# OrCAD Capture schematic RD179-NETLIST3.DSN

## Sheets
1 3: size A3
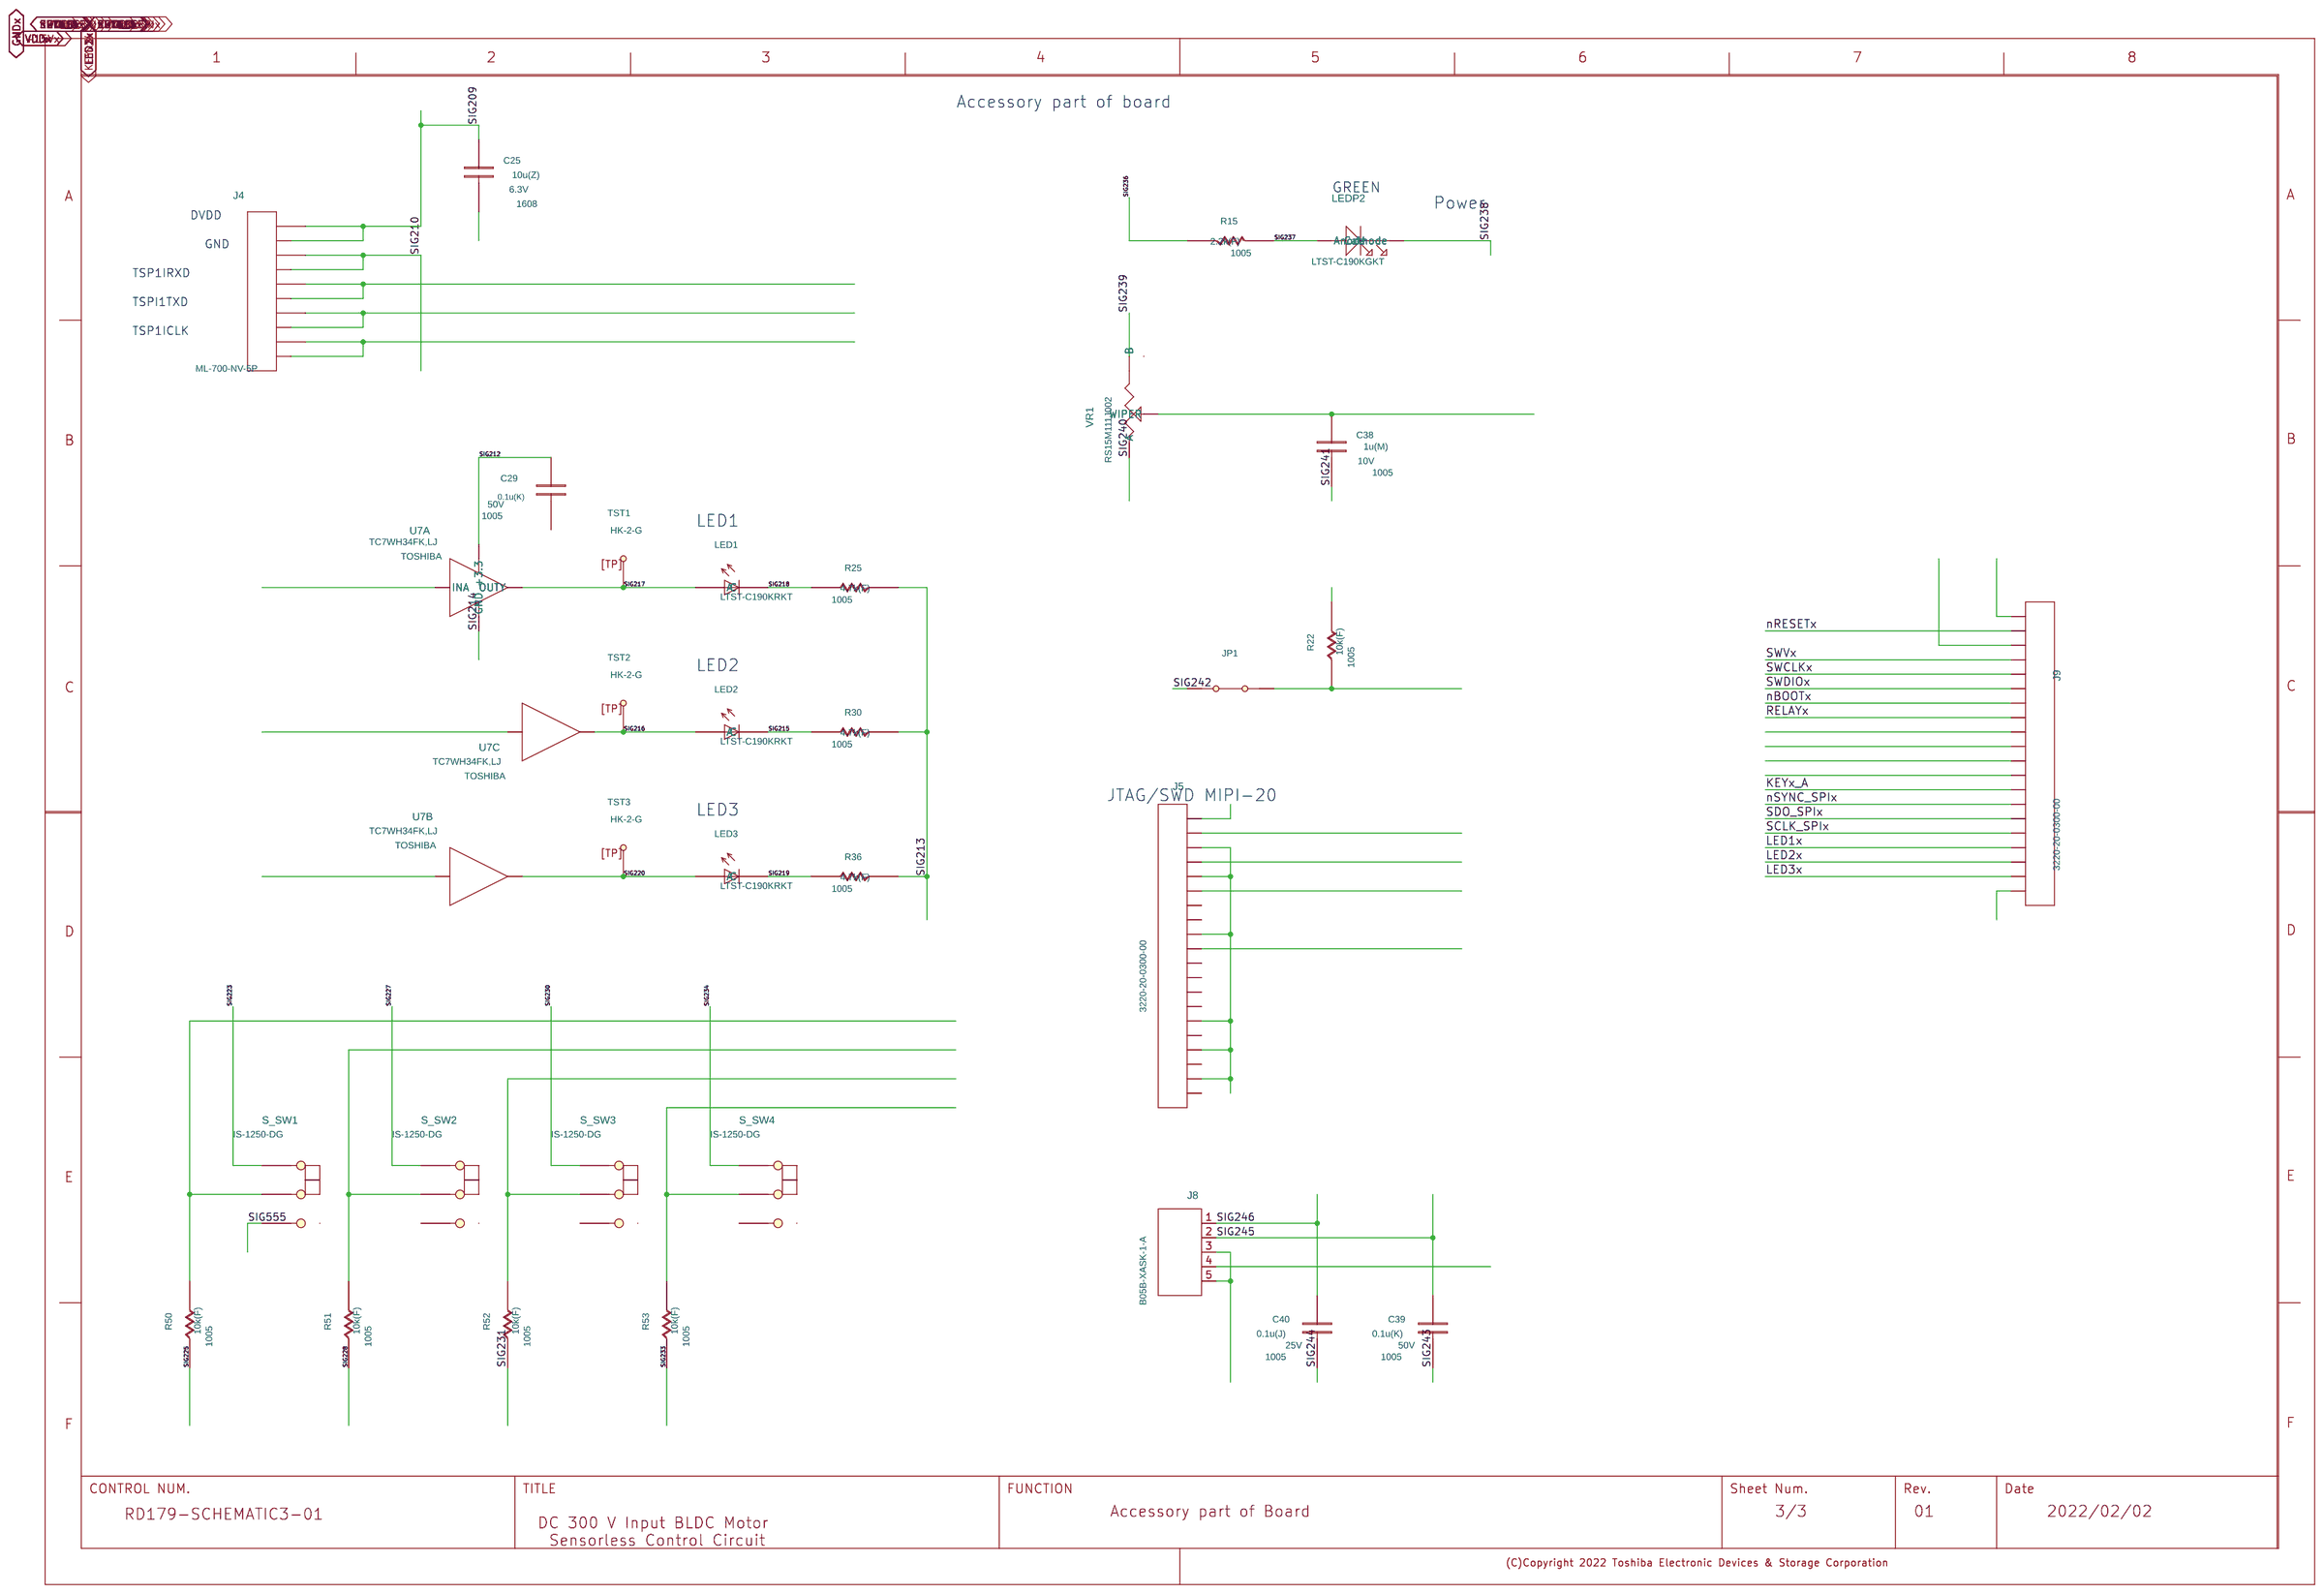
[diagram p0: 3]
2 2: size A3
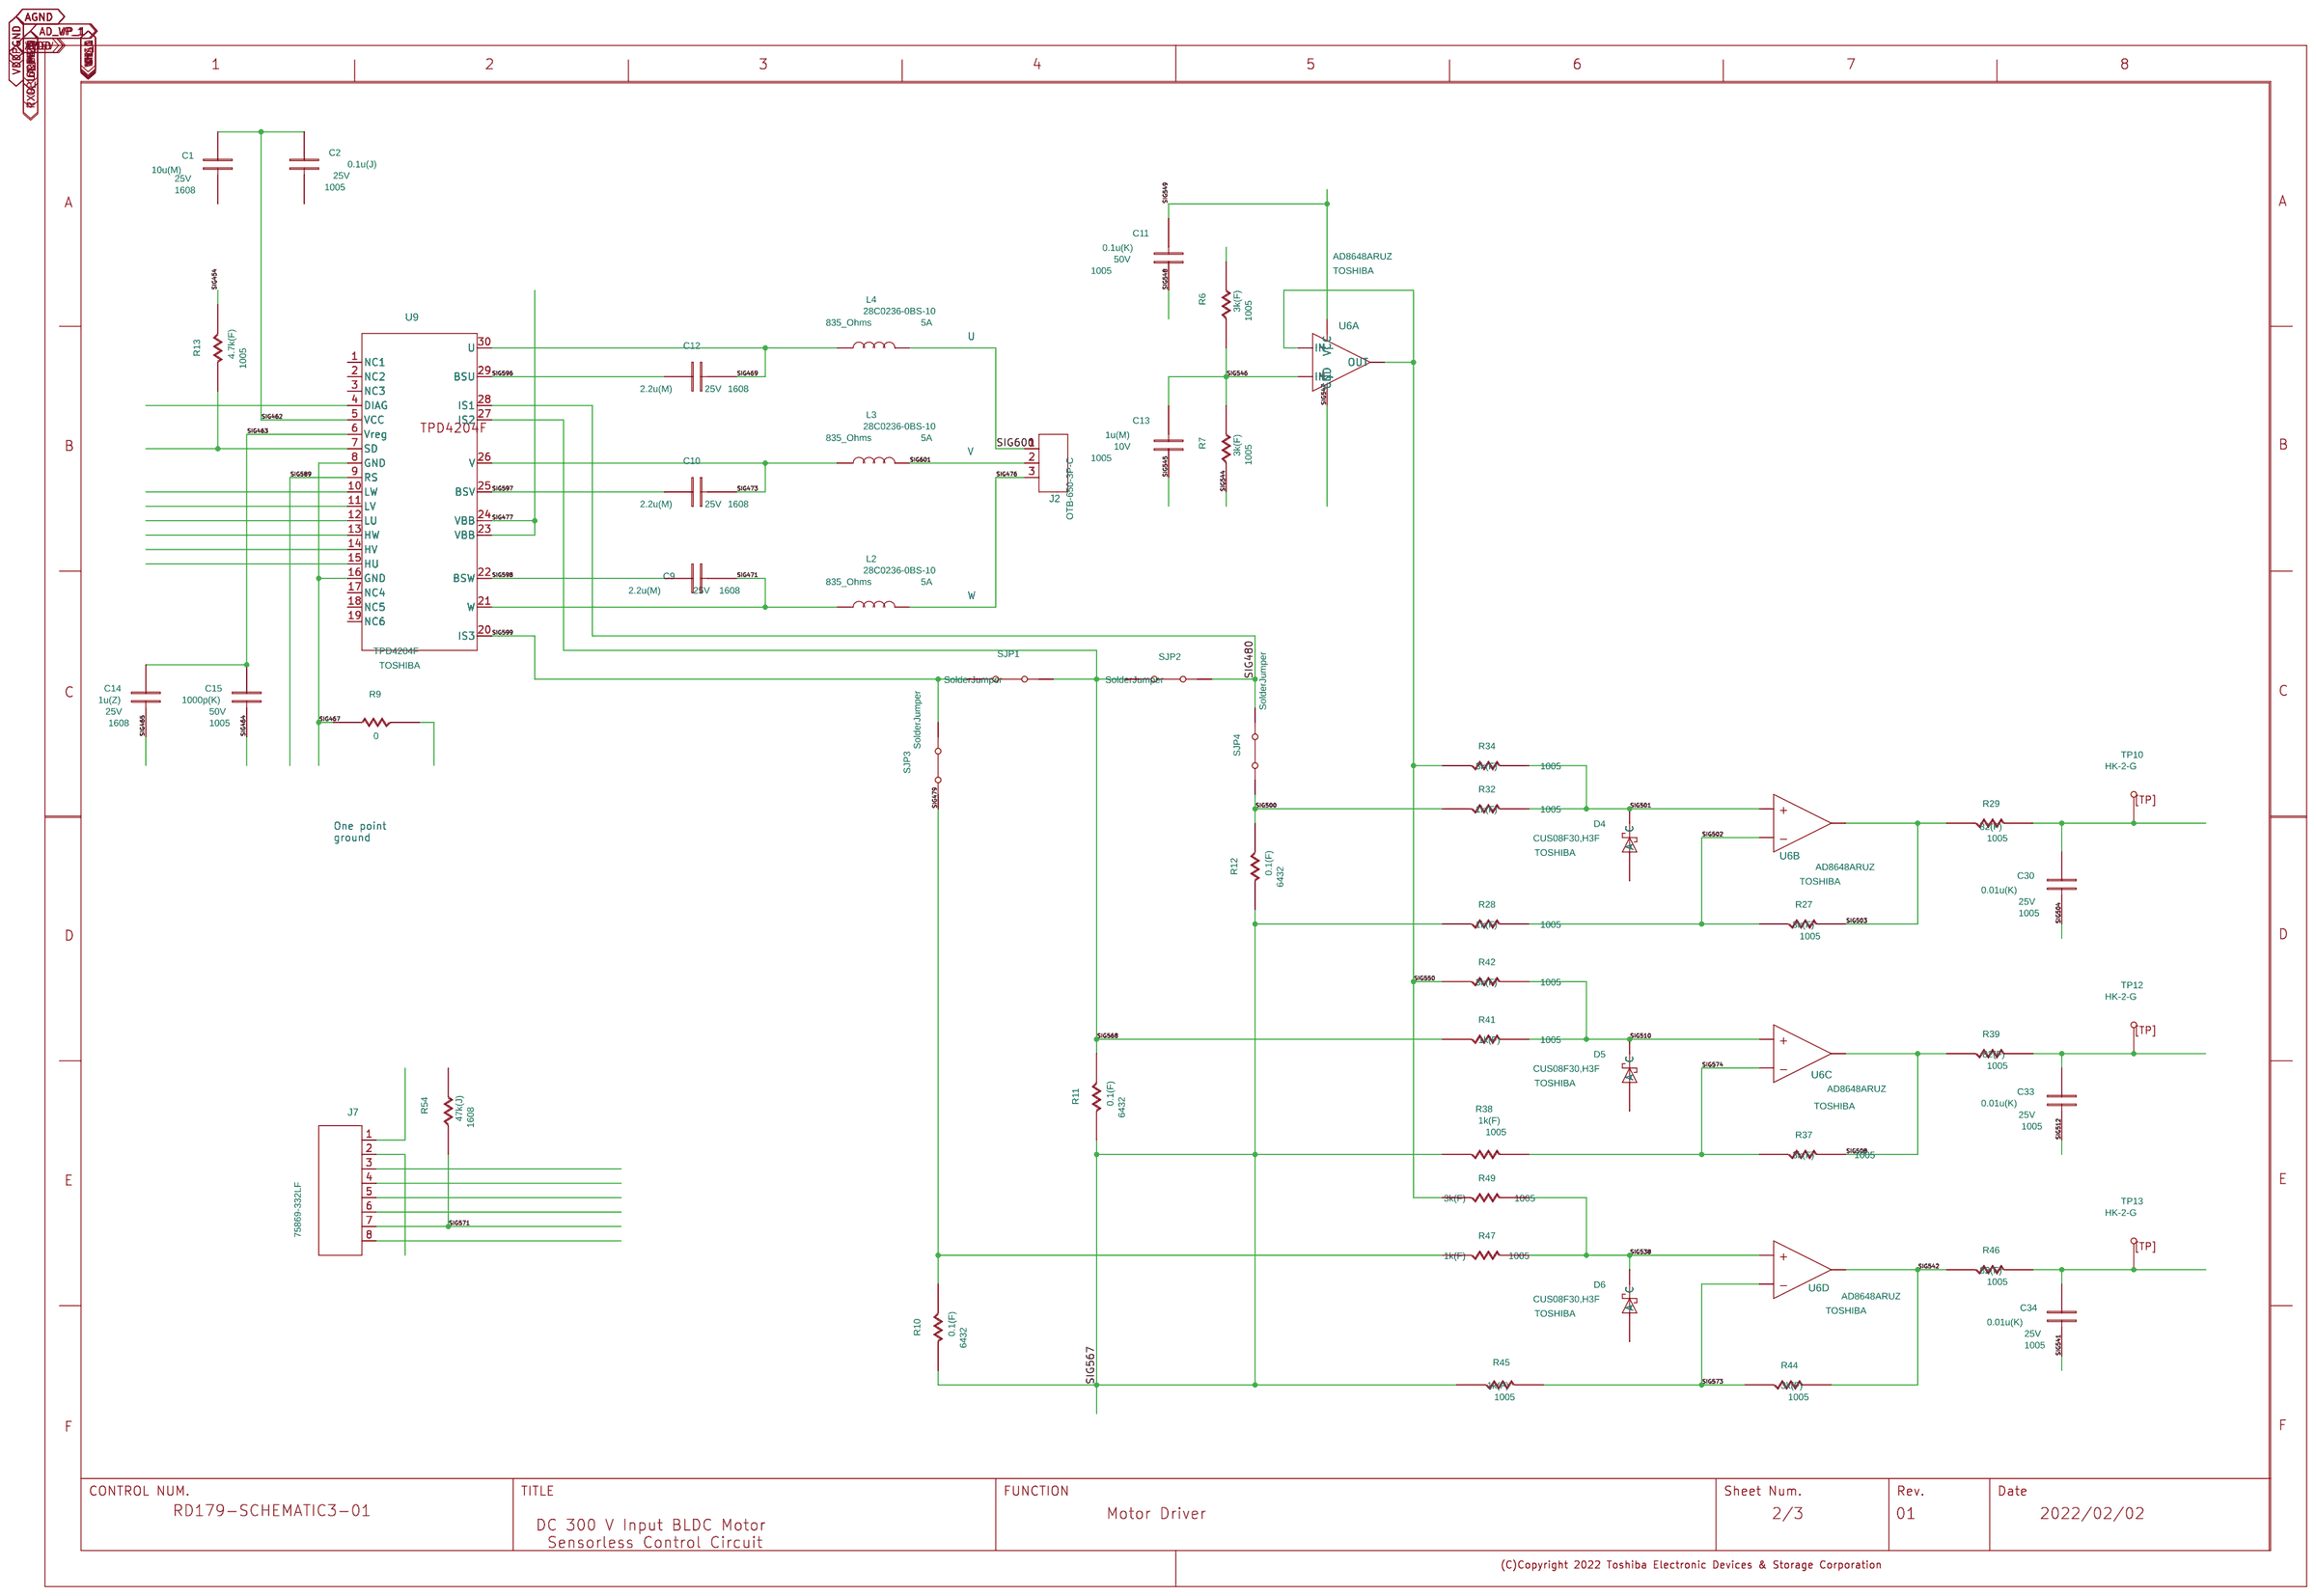
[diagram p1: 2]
3 1: size A3
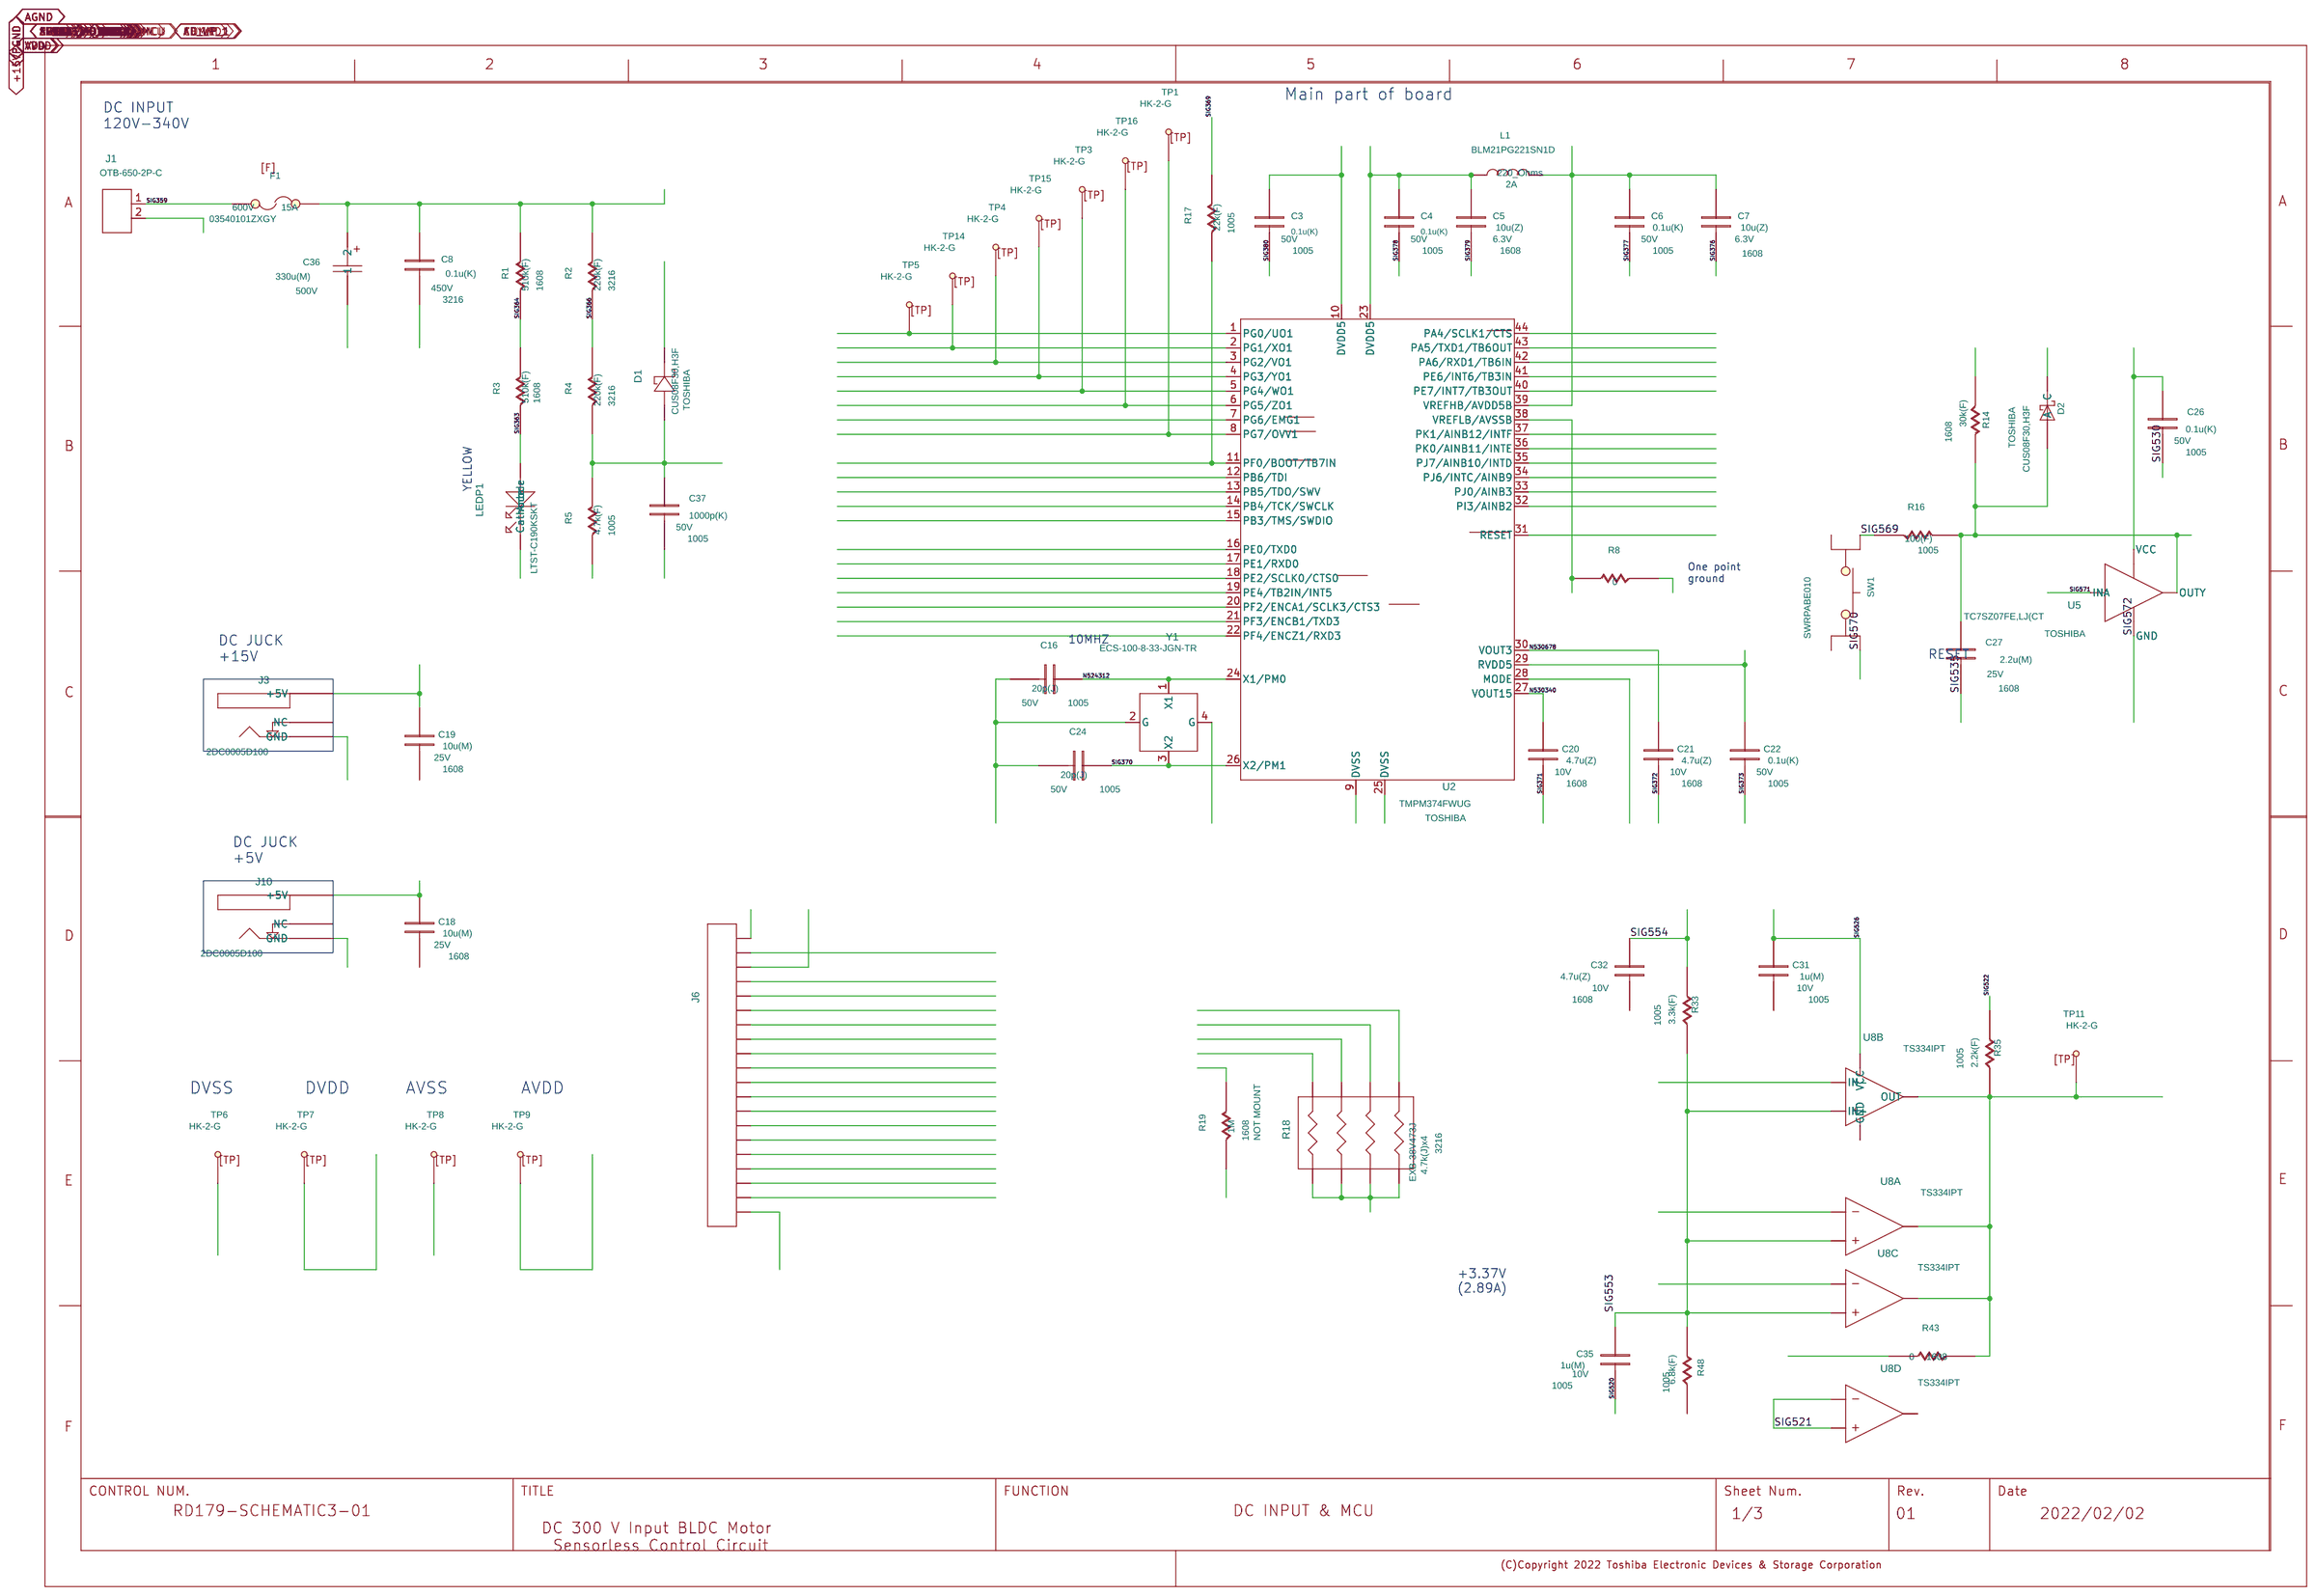
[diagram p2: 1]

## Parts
sheet 1
C3  C
C4  C
C5  C
C6  C
C7  C
C8  C
C16  C
C18  C
C19  C
C20  C
C21  C
C22  C
C24  C
C26  C
C27  C
C31  C
C32  C
C35  C
C36  CP
C37  C
D1  CUS08F30
D2  SBD
F1  F
J1  OTB-650-2P-C
J3  DCJACK
J6  3220-20-0300-00
J10  DCJACK
L1  L
LEDP1  LTST-C190KSKT  [LED]
R1  R
R2  R
R3  R
R4  R
R5  R
R8  R
R14  R
R16  R
R17  R
R18  EXB-38V473J
R19  R
R33  R
R35  R
R43  R
R48  R
SW1  SWRPABE010
TP1  TP
TP3  TP
TP4  TP
TP5  TP
TP6  TP
TP7  TP
TP8  TP
TP9  TP
TP11  TP
TP14  TP
TP15  TP
TP16  TP
U2  TMPM374FWUG
U5  SN74LVC1G07DRLR_1
U8  LMV339IPT_2  (sections A,B,C,D)
U?#2  WAKU_DEF100
Y1  XTAL_ECS_100_8_33_10_000MHZ
sheet 2
C1  C
C2  C
C9  C
C10  C
C11  C
C12  C
C13  C
C14  C
C15  C
C30  C
C33  C
C34  C
D4  SBD
D5  SBD
D6  SBD
J2  OTB-650-3P-C
J7  75869-332LF
L2  L
L3  L
L4  L
R6  R
R7  R
R9  R
R10  R
R11  R
R12  R
R13  R
R27  R
R28  R
R29  R
R32  R
R34  R
R37  R
R38  R
R39  R
R41  R
R42  R
R44  R
R45  R
R46  R
R47  R
R49  R
R54  R
SJP1  JP
SJP2  JP
SJP3  JP
SJP4  JP
TP10  TP
TP12  TP
TP13  TP
U6  AD8648ARUZ_1  (sections A,B,C,D)
U9  TPD4204F
U?#1  WAKU_DEF100
sheet 3
C25  C
C29  C
C38  C
C39  C
C40  C
J4  ML_700_NH_5P
J5  3220-20-0300-00
J8  B05B-XASK-1-A
J9  3220-20-0300-00
JP1  JP
LED1  LED
LED2  LED
LED3  LED
LEDP2  LTST-C190KGKT  [LED]
R15  R
R22  R
R25  R
R30  R
R36  R
R50  R
R51  R
R52  R
R53  R
S_SW1  SW_IS_1250
S_SW2  SW_IS_1250
S_SW3  SW_IS_1250
S_SW4  SW_IS_1250
TST1  TP
TST2  TP
TST3  TP
U7  SN74LVC3G17DCUR_1  (sections A,B,C)
U?#3  WAKU_DEF100
VR1  VR

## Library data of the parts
C3 C4 C6 C11 C22 C26 C29 C39 = C: COMP: CRC-1005-DEF; COMPONENTTYPE: 4; SIZECODESMD: 1005; VAL1: 0.1u(K); VAL2: 50V
C5 C7 C25 = C: COMP: CRC-1608-DEF; COMPONENTTYPE: 4; SIZECODESMD: 1608; VAL1: 10u(Z); VAL2: 6.3V
C8 = C: COMP: CC-3216-DEF; COMPONENTTYPE: 4; SIZECODESMD: 3216; VAL1: 0.1u(K); VAL2: 450V
C16 C24 = C: COMP: CRC-1005-DEF; COMPONENTTYPE: 4; SIZECODESMD: 1005; VAL1: 20p(J); VAL2: 50V
C1 C18 C19 = C: COMP: CRC-1608-DEF; COMPONENTTYPE: 4; SIZECODESMD: 1608; VAL1: 10u(M); VAL2: 25V
C20 C21 C32 = C: COMP: CRC-1608-DEF; COMPONENTTYPE: 4; SIZECODESMD: 1608; VAL1: 4.7u(Z); VAL2: 10V
C9 C10 C12 C27 = C: COMP: CRC-1608-DEF; COMPONENTTYPE: 4; SIZECODESMD: 1608; VAL1: 2.2u(M); VAL2: 25V
C13 C31 C35 C38 = C: COMP: CRC-1005-DEF; COMPONENTTYPE: 4; SIZECODESMD: 1005; VAL1: 1u(M); VAL2: 10V
C36 = CP: COMP: DDC-3000-00; COMPONENTTYPE: 4; VAL1: 330u(M); VAL2: 500V
C15 C37 = C: COMP: CRC-1005-DEF; COMPONENTTYPE: 4; SIZECODESMD: 1005; VAL1: 1000p(K); VAL2: 50V
D1 = DIODE_SB1003M3: COMP: CD-USC-05; COMPONENTTYPE: 4; INSTANCENAME: I16849034; TIME: 16:32:01; UPDATETIME: 16:32:01; USERCOMPTEXT3: TOSHIBA; VAL1: CUS08F30,H3F; VAL3: CUS08F30,H3F
D2 D4-D6 = SBD: COMP: CD-USC-05; COMPONENTTYPE: 4; USERCOMPTEXT3: TOSHIBA; VAL1: CUS08F30,H3F; VAL3: CUS08F30,H3F
F1 = F: COMP: DFU-3512-00; COMPONENTTYPE: 4; VAL1: 600V; VAL2: 15A; VAL3: 03540101ZXGY
J1 = OTB_650_2P_C: COMP: OTB-650-2P_R00; COMPONENTTYPE: 4; INSTANCENAME: I00689; SAVECOUNT: 1; UPDATETIME: 16:32:00
J3 = DCJACK: COMP: 2DC-0005D100_R00; COMPONENTTYPE: 4; INSTANCENAME: I16855658; SAVECOUNT: 1; UPDATETIME: 16:32:01; VAL1: 2DC0005D100; VAL3: 2DC0005D100
J6 = CON20: COMP: 3220-20-0300-00_R00; COMPONENTKIND: 135; COMPONENTTYPE: 4; INSTANCENAME: I17020784; SAVECOUNT: 1; UPDATETIME: 16:32:01
J10 = DCJACK: COMP: 2DC-0005D100_R00; COMPONENTTYPE: 4; INSTANCENAME: I17047111; SAVECOUNT: 1; UPDATETIME: 16:32:01; VAL1: 2DC0005D100; VAL3: 2DC0005D100
L1 = L: COMP: CL-2125-DEF; COMPONENTTYPE: 4; VAL1: 220_Ohms; VAL2: 2A; VAL3: BLM21PG221SN1D
LEDP1 = LED_3RED: COMP: LTST-C190_R00; COMPONENTKIND: 104; COMPONENTTYPE: 4; INSTANCENAME: I16843725
R1 R3 = R: COMP: CRC-1608-DEF; COMPONENTTYPE: 4; SIZECODESMD: 1608; VAL1: 510k(F); VAL2: 250mW
R2 R4 = R: COMP: CR-3216-DEF; COMPONENTTYPE: 4; SIZECODESMD: 3216; VAL1: 220k(F); VAL2: 250mW
R5 R13 R25 R30 R36 = R: COMP: CRC-1005-DEF; COMPONENTTYPE: 4; SIZECODESMD: 1005; VAL1: 4.7k(F); VAL2: 63mW
R8 R9 = R: COMP: CX-0002-75; COMPONENTTYPE: 4; VAL1: 0
R14 = R: COMP: CRC-1608-58; COMPONENTTYPE: 4; SIZECODESMD: 1608; VAL1: 30k(F); VAL2: 100mW
R16 = R: COMP: CRC-1005-DEF; COMPONENTTYPE: 4; SIZECODESMD: 1005; VAL1: 100(F); VAL2: 100mW
R17 = R: COMP: CRC-1005-DEF; COMPONENTTYPE: 4; SIZECODESMD: 1005; VAL1: 22k(F); VAL2: 100mW
R18 = EXB_38V: COMP: CRA-3216-33; COMPONENTTYPE: 4; INSTANCENAME: I17038151; SAVECOUNT: 1; SIZECODESMD: 3216; UPDATETIME: 16:32:00; VAL1: 4.7k(J)x4; VAL2: 63w
R19 = R: COMP: CRC-1608-DEF; COMPONENTTYPE: 4; NOTMOUNT: NOT MOUNT; SIZECODESMD: 1608; VAL1: 1M; VAL2: 100mW
R33 = R: COMP: CRC-1005-DEF; COMPONENTTYPE: 4; SIZECODESMD: 1005; VAL1: 3.3k(F); VAL2: 100mW
R15 R35 = R: COMP: CRC-1005-DEF; COMPONENTTYPE: 4; SIZECODESMD: 1005; VAL1: 2.2k(F); VAL2: 100mW
R43 = R: COMP: CRC-1608-DEF; COMPONENTTYPE: 4; SIZECODESMD: 1608; VAL1: 0; VAL2: 100mW
R48 = R: COMP: CRC-1005-12; COMPONENTTYPE: 4; SIZECODESMD: 1005; VAL1: 6.8k(F); VAL2: 63mW
SW1 = SWRPABE010: COMP: SKRPABE010_R01; COMPONENTTYPE: 4
TP1 TP3-TP16 TST1-TST3 = TP: COMP: HK-2-G; COMPONENTTYPE: 4; VAL1: HK-2-G; VAL3: HK-2-G
U2 = TMPM374FWUG: COMPONENTTYPE: 4; USERCOMPTEXT3: TOSHIBA
U5 = SN74LVC1G07DRLR_1: COMP: TC7SZ07FE; COMPONENTKIND: 101; COMPONENTTYPE: 4; USERCOMPTEXT3: TOSHIBA; VAL1: TC7SZ07FE,LJ(CT; VAL3: TC7SZ07FE,LJ(CT
U8 = LMV339IPT_2: COMP: TS334IPT; COMPONENTTYPE: 8; CaptureCellPackProp: LMV339IPT_2A; FUNCN: TS334IPT_2; VAL1: TS334IPT; VAL3: TS334IPT
U?#2 = WAKU_DEF100: COMPONENTTYPE: 2; DATE: 2022/02/02; DRAWINGNUMBER: RD179-SCHEMATIC3-01; FUNCTION: DC INPUT & MCU; REVISION: 01; SAVEAREA0: 147884,-66467,487065,89883; SAVECOUNT: 7; SHEETNUMBER: 1/3; TITLE: DC 300 V Input BLDC Motor / Sensorless Control Circuit; UPDATEDATE: 2022/02/03; UPDATETIME: 12:53:04
Y1 = XTAL_ECS_100_8_33_10_000MHZ: COMP: CXL-3225-68; COMPONENTKIND: 101; COMPONENTTYPE: 4; VAL1: ECS-100-8-33-JGN-TR; VAL3: ECS-100-8-33-JGN-TR
C2 C40 = C: COMP: CRC-1005-DEF; COMPONENTTYPE: 4; SIZECODESMD: 1005; VAL1: 0.1u(J); VAL2: 25V
C14 = C: COMP: CRC-1608-DEF; COMPONENTTYPE: 4; SIZECODESMD: 1608; VAL1: 1u(Z); VAL2: 25V
C30 C33 C34 = C: COMP: CRC-1005-DEF; COMPONENTTYPE: 4; SIZECODESMD: 1005; VAL1: 0.01u(K); VAL2: 25V
J2 = OTB_650_3P_C: COMP: OTB-650-3P_R00; COMPONENTTYPE: 4; INSTANCENAME: I541179; SAVECOUNT: 1; UPDATETIME: 16:31:59
J7 = CON8: COMP: 75869-332LF_R00; COMPONENTKIND: 135; COMPONENTTYPE: 4; INSTANCENAME: I16797633; SAVECOUNT: 1; UPDATETIME: 16:31:59
L2-L4 = L: COMP: DL-1460-01; COMPONENTTYPE: 4; VAL1: 835_Ohms; VAL2: 5A; VAL3: 28C0236-0BS-10
R6 R7 R27 R34 R37 R42 R44 R49 = R: COMP: CRC-1005-DEF; COMPONENTTYPE: 4; SIZECODESMD: 1005; VAL1: 3k(F); VAL2: 100mW
R10-R12 = R: COMP: CR-6432-18; COMPONENTTYPE: 4; SIZECODESMD: 6432; VAL1: 0.1(F); VAL2: 3W
R28 R32 R38 R41 R45 R47 = R: COMP: CRC-1005-DEF; COMPONENTTYPE: 4; SIZECODESMD: 1005; VAL1: 1k(F); VAL2: 100mW
R29 R39 R46 = R: COMP: CRC-1005-DEF; COMPONENTTYPE: 4; SIZECODESMD: 1005; VAL1: 82(F); VAL2: 63mW
R54 = R: COMP: CRC-1608-DEF; COMPONENTTYPE: 4; SIZECODESMD: 1608; VAL1: 47k(J); VAL2: 100mW
SJP1-SJP4 = JP: COMP: CJP-0002-116; COMPONENTTYPE: 4; VAL1: SolderJumper; VAL3: SolderJumper
U6 = AD8648ARUZ_1: COMPONENTTYPE: 4; CaptureCellPackProp: AD8648ARUZ_1A; USERCOMPTEXT3: TOSHIBA; VAL1: AD8648ARUZ; VAL3: AD8648ARUZ
U9 = TPD4204F: COMPONENTTYPE: 4; USERCOMPTEXT3: TOSHIBA
U?#1 = WAKU_DEF100: COMPONENTTYPE: 2; DATE: 2022/02/02; DRAWINGNUMBER: RD179-SCHEMATIC3-01; FUNCTION: Motor Driver; REVISION: 01; SAVEAREA0: 147884,-66467,487065,89883; SAVECOUNT: 7; SHEETNUMBER: 2/3; TITLE: DC 300 V Input BLDC Motor / Sensorless Control Circuit; UPDATEDATE: 2022/02/03; UPDATETIME: 11:31:06
J4 = ML_700_NH_5P: COMP: ML-700-NV-5P_R00; COMPONENTTYPE: 4; VAL1: ML-700-NV-5P; VAL3: ML-700-NV-5P
J5 = CON20: COMP: 3220-20-0300-00_R00; COMPONENTKIND: 135; COMPONENTTYPE: 4; INSTANCENAME: I16846450; SAVECOUNT: 1; UPDATETIME: 16:32:01
J8 = B05B_XASK_1_A: COMP: B05B-XASK-1-A_R00; COMPONENTKIND: 135; COMPONENTTYPE: 4; INSTANCENAME: I16947079; SAVECOUNT: 1; UPDATETIME: 16:31:59
J9 = CON20: COMP: 3220-20-0300-00_R00; COMPONENTKIND: 135; COMPONENTTYPE: 4; INSTANCENAME: I17018983; SAVECOUNT: 1; UPDATETIME: 16:32:01
JP1 = JP: COMP: PH-1X02SG_R00; COMPONENTTYPE: 4; VAL1: PH-1x40SG; VAL3: PH-1x40SG
LED1-LED3 = LED: COMP: LTST-C190_R00; COMPONENTTYPE: 4; VAL1: LTST-C190KRKT; VAL3: LTST-C190KRKT
LEDP2 = LED_3RED: COMP: LTST-C190_R00; COMPONENTKIND: 104; COMPONENTTYPE: 4; INSTANCENAME: I16847094
R22 R50-R53 = R: COMP: CRC-1005-DEF; COMPONENTTYPE: 4; SIZECODESMD: 1005; VAL1: 10k(F); VAL2: 100mW
S_SW1-S_SW4 = SW_IS_1250: COMP: IS-1250_R00; COMPONENTTYPE: 4; VAL1: IS-1250-DG; VAL3: IS-1250-DG
U7 = SN74LVC3G17DCUR_1: COMP: TC7WH34FK; COMPONENTTYPE: 8; CaptureCellPackProp: SN74LVC3G17DCUR_1B; FUNCN: TC7WH34FK_LJ_3; USERCOMPTEXT3: TOSHIBA; VAL1: TC7WH34FK,LJ; VAL3: TC7WH34FK,LJ
U?#3 = WAKU_DEF100: COMPONENTTYPE: 2; DATE: 2022/02/02; DRAWINGNUMBER: RD179-SCHEMATIC3-01; FUNCTION: Accessory part of Board; REVISION: 01; SAVEAREA0: 147884,-66467,487065,89883; SAVECOUNT: 7; SHEETNUMBER: 3/3; TITLE: DC 300 V Input BLDC Motor / Sensorless Control Circuit; UPDATEDATE: 2022/02/03; UPDATETIME: 12:53:05
VR1 = VR: COMP: RS15M111J002_R00; COMPONENTTYPE: 4; VAL1: RS15M111J002; VAL3: RS15M111J002

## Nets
+15V: C1.1 C2.1 C19.1 J3.1(+5V) J6.3 U9.5(VCC)
+15Vx: C40.1 J8.1 J9.3
AGND: C1.2 C2.2 C3.1 C3.2 C4.1 C4.2 C5.1 C5.2 C6.2 C7.2 C11.1 C13.1 C14.2 C15.2 C16.2 C18.1 C18.2 C19.2 C20.2 C21.2 C22.1 C22.2 C24.2 C26.1 C26.2 C27.2 C30.2 C31.2 C32.2 C33.2 C34.2 C35.2 D1.3(CATHODE) D2.3(C) D4.1(A) D5.1(A) D6.1(A) J3.2(GND) J6.1 J6.20 J7.1 J7.2 J10.1(+5V) J10.2(GND) L1.2 R7.2 R8.1 R8.2 R9.1 R13.2 R14.2 R17.1 R18.1 R18.2 R18.3 R18.4 R19.2 R35.1 R48.2 R54.1 SW1.4 TP6.1 TP7.1 TP8.1 U2.9(DVSS) U2.10(DVDD5) U2.23(DVDD5) U2.25(DVSS) U2.28(MODE) U2.29(RVDD5) U2.38(VREFLB/AVSSB) U5.3(GND) U5.5(VCC) U6.11(GND) U8.10 U8.11 U8.12(GND) U9.8(GND) U9.9(RS) U9.16(GND) Y1.2(G) Y1.4(G)
AVDD: C6.1 C7.1 C11.2 C31.1 C32.1 L1.1 R6.1 R33.1 TP9.1 U2.39(VREFHB/AVDD5B) U6.4(VCC) U8.3(VCC)
GNDx: C25.2 C29.2 C38.2 C39.2 C40.2 J4.2 J4.2-2 J5.3 J5.5 J5.9 J5.15 J5.17 J5.19 J8.3 J8.5 J9.20 JP1.2 LEDP2.2(Cathode) R25.2 R30.2 R36.2 R50.2 R51.2 R52.2 R53.2 S_SW1.3 S_SW2.3 S_SW3.3 S_SW4.3 U7.4(GND) VR1.1(A)
PGND: C8.2 C36.2(1) C37.2 J1.2 LEDP1.2(Cathode) R5.2 R9.2 R10.1 R11.1 R12.1 R28.2 R38.2 R45.2
VDDx: C25.1 C29.1 C39.1 J4.1 J4.1-2 J5.1 J8.2 J9.1 R15.2 R22.1 S_SW1.1 S_SW2.1 S_SW3.1 S_SW4.1 U7.8(+3.3) VR1.3(B)
AD_UP_1: C30.1 R29.1 TP10.1 U2.32(PI3/AINB2) U8.4(IN-)
AD_VDC_1: C37.1 D1.1(ANODE) R4.2 R5.1 U2.35(PJ7/AINB10/INTD)
AD_VP_1: C33.1 R39.1 TP12.1 U2.33(PJ0/AINB3) U8.6
AD_WP_1: C34.1 R46.1 TP13.1 U2.34(PJ6/INTC/AINB9) U8.8
COMMD: J6.10 J7.6 R18.6 U2.40(PE7/INT7/TB3OUT)
DIAG: R43.1 U9.4(DIAG)
GPIO_MAIN: J7.8 U2.18(PE2/SCLK0/CTS0)
KEY_1: J6.9 J7.5 R18.5 U2.41(PE6/INT6/TB3IN)
KEY_3: J6.11 R18.7 U2.37(PK1/AINB12/INTF)
KEY_4: J6.12 R18.8 U2.12(PB6/TDI)
KEY_A: J6.13 R19.1 U2.36(PK0/AINB11/INTE)
KEYx_1: J9.9 R50.1 S_SW1.2
KEYx_2: J9.10 R51.1 S_SW2.2
KEYx_3: J9.11 R52.1 S_SW3.2
KEYx_4: J9.12 R53.1 S_SW4.2
KEYx_A: C38.1 J9.13 VR1.2(WIPER)
LED1: J6.17 U2.20(PF2/ENCA1/SCLK3/CTS3)
LED1x: J9.17 U7.1(INA)
LED2: J6.18 U2.21(PF3/ENCB1/TXD3)
LED2x: J9.18 U7.3
LED3: J6.19 U2.22(PF4/ENCZ1/RXD3)
LED3x: J9.19 U7.6
nBOOT: J6.7 R17.2 U2.11(PF0/BOOT/TB7IN)
nBOOTx: J9.7 JP1.1 R22.2
nEMG: R35.2 R43.2 TP11.1 U2.7(PG6/EMG1) U8.1 U8.2(OUT) U8.14
nRESET: C27.1 D2.1(A) J6.2 R14.1 R16.1 U2.31(RESET) U5.4(OUTY)
nRESETx: J5.10 J9.2
nRESIN: J7.7 R54.2 U5.2(INA)
nSD: R13.1 U2.19(PE4/TB2IN/INT5) U9.7(SD)
nSYNC_SPI: J6.14 U2.42(PA6/RXD1/TB6IN)
nSYNC_SPIx: J4.3 J4.3-2 J9.14
RELAY: J6.8 TP1.1 U2.8(PG7/OVV1)
RELAYx: J8.4 J9.8
RXD_UA_MCU: J7.3 U2.17(PE1/RXD0)
SCLK_SPI: J6.16 U2.44(PA4/SCLK1/CTS)
SCLK_SPIx: J4.5 J4.5-2 J9.16
SDO_SPI: J6.15 U2.43(PA5/TXD1/TB6OUT)
SDO_SPIx: J4.4 J4.4-2 J9.15
SIG215: LED2.2(C) R30.1
SIG216: LED2.1(A) TST2.1 U7.5
SIG217: LED1.1(A) TST1.1 U7.7(OUTY)
SIG218: LED1.2(C) R25.1
SIG219: LED3.2(C) R36.1
SIG220: LED3.1(A) TST3.1 U7.2
SIG237: LEDP2.1(Anode) R15.1
SIG359: F1.1 J1.1
SIG363: LEDP1.1(Anode) R3.2
SIG364: R1.2 R3.1
SIG366: R2.2 R4.1
SIG370: C24.1 U2.26(X2/PM1) Y1.3(X2)
SIG463: C14.1 C15.1 U9.6(Vreg)
SIG469: C12.2 L4.2 U9.30(U)
SIG471: C9.2 L2.2 U9.21(W)
SIG473: C10.2 L3.2 U9.26(V)
SIG476: J2.3 L2.1
SIG479: R10.2 R47.2 SJP3.1
SIG480: SJP2.2 SJP4.2 U9.28(IS1)
SIG500: R12.2 R32.2 SJP4.1
SIG501: D4.3(C) R32.1 R34.1 U6.5
SIG502: R27.2 R28.1 U6.6
SIG503: R27.1 R29.2 U6.7
SIG508: R37.1 R39.2 U6.8
SIG510: D5.3(C) R41.1 R42.1 U6.10
SIG538: D6.3(C) R47.1 R49.1 U6.12
SIG542: R44.1 R46.2 U6.14
SIG546: C13.2 R6.2 R7.1 U6.3(IN+)
SIG550: R34.2 R42.2 R49.2 U6.1(OUT) U6.2(IN-)
SIG553: C35.1 R33.2 R48.1 U8.5(IN+) U8.7 U8.9
SIG568: R11.2 R41.2 SJP1.2 SJP2.1 U9.27(IS2)
SIG569: R16.2 SW1.2
SIG573: R44.2 R45.1 U6.13
SIG574: R37.2 R38.1 U6.9
SIG596: C12.1 U9.29(BSU)
SIG597: C10.1 U9.25(BSV)
SIG598: C9.1 U9.22(BSW)
SIG599: SJP1.1 SJP3.2 U9.20(IS3)
SIG600: J2.1 L4.1
SIG601: J2.2 L3.1
SWCLK: J6.5 U2.14(PB4/TCK/SWCLK)
SWCLKx: J5.4 J9.5
SWDIO: J6.6 U2.15(PB3/TMS/SWDIO)
SWDIOx: J5.2 J9.6
SWV: J6.4 U2.13(PB5/TDO/SWV)
SWVx: J5.6 J9.4
TXD_UA_MCU: J7.4 U2.16(PE0/TXD0)
UH_1: TP5.1 U2.1(PG0/UO1) U9.15(HU)
UL_1: TP14.1 U2.2(PG1/XO1) U9.12(LU)
VH_1: TP4.1 U2.3(PG2/VO1) U9.14(HV)
VL_1: TP15.1 U2.4(PG3/YO1) U9.11(LV)
VP+: C8.1 C36.1(2) F1.2 R1.1 R2.1 U9.23(VBB) U9.24(VBB)
WH_1: TP3.1 U2.5(PG4/WO1) U9.13(HW)
WL_1: TP16.1 U2.6(PG5/ZO1) U9.10(LW)
N524312: C16.1 U2.24(X1/PM0) Y1.1(X1)
N530340: C20.1 U2.27(VOUT15)
N530678: C21.1 U2.30(VOUT3)

Not connected (* = marked no-connect by the designer): J3 3(NC); J5 7 8 11 12 13 14 16 18 20; J10 3(NC); S_SW1 4 5 6; S_SW2 4 5 6; S_SW3 4 5 6; S_SW4 4 5 6; SW1 1 3; U5 1; U8 13; U9 1(NC1) 2(NC2) 3(NC3) 17(NC4) 18(NC5) 19(NC6); VR1 4

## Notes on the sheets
sheet 1
- Accessory part of board
- GREEN
- Power
- DVDD
- GND
- TSP1IRXD
- TSPI1TXD
- TSP1ICLK
- LED1
- LED2
- JTAG/SWD MIPI-20
- LED3
sheet 2
- U
- V
- W
- One point
  ground
sheet 3
- Main part of board
- DC INPUT
  120V-340V
- YELLOW
- One point
  ground
- DC JUCK
  +15V
- 10MHZ
- RESET
- DC JUCK
  +5V
- DVSS
- DVDD
- AVSS
- AVDD
- +3.37V
  (2.89A)
